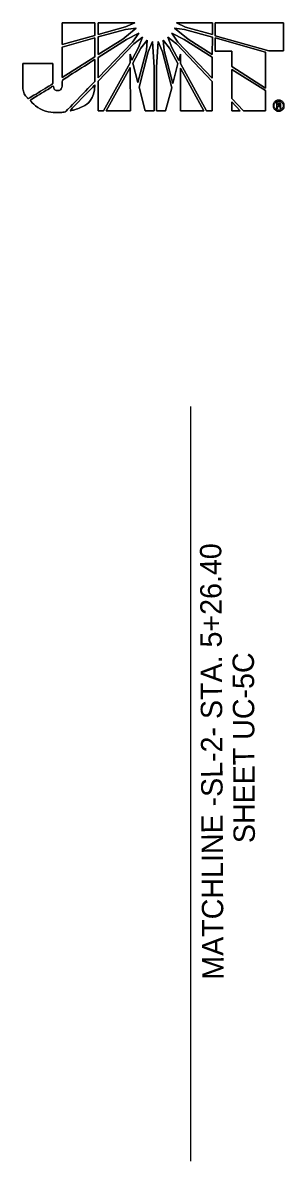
# Model space of a CAD drawing. Extents: x 0 to 2694, y -754 to 1499.
# Drawn here: x 3.571 to 3.775, y 0.255 to 1.142 of the extents above; entities that cross this region are included whole.
import ezdxf

# ---------------------------------------------------------------- set-up
doc = ezdxf.new("R2010")
doc.units = 0
doc.layers.add('Layer 1', color=7, linetype='Continuous')
doc.layers.add('UC Plan Profile Sheet 34 CELL', color=7, linetype='Continuous')

# ---------------------------------------------------------------- blocks, each defined once
blk = doc.blocks.new('block 2_1')
at = {"layer": 'Layer 1'}
for p, q in [((0.10682, 0.1325), (0.10682, 0.14026)), ((0.10682, 0.14026), (0.11852, 0.14026)), ((0.11852, 0.14026), (0.11852, 0.13575)), ((0.11973, 0.13613), (0.11973, 0.14032)), ((0.11973, 0.14032), (0.1329, 0.14032)), ((0.1329, 0.14032), (0.12954, 0.13884)), ((0.15109, 0.13878), (0.14781, 0.14032)), ((0.14781, 0.14032), (0.16078, 0.14026)), ((0.16078, 0.14026), (0.16078, 0.13606)), ((0.16169, 0.1358), (0.16169, 0.14032)), ((0.16169, 0.14032), (0.18629, 0.14032)), ((0.18629, 0.14032), (0.18629, 0.13024)), ((0.11852, 0.13575), (0.10682, 0.1325)), ((0.10682, 0.13161), (0.11852, 0.1349)), ((0.11852, 0.1349), (0.11852, 0.12812)), ((0.12954, 0.13884), (0.11973, 0.13613)), ((0.11973, 0.13523), (0.12954, 0.13793)), ((0.11973, 0.12889), (0.11973, 0.13523)), ((0.13337, 0.13839), (0.12852, 0.13445)), ((0.12954, 0.13793), (0.13337, 0.13839)), ((0.12987, 0.13432), (0.13433, 0.13658)), ((0.13433, 0.13658), (0.13207, 0.13341)), ((0.13257, 0.13277), (0.13568, 0.13517)), ((0.13568, 0.13517), (0.13425, 0.13142)), ((0.14476, 0.13517), (0.14787, 0.13277)), ((0.14619, 0.13142), (0.14476, 0.13517)), ((0.14613, 0.13658), (0.15065, 0.13432)), ((0.14839, 0.13335), (0.14613, 0.13658)), ((0.14715, 0.13839), (0.15076, 0.13793)), ((0.15206, 0.13438), (0.14715, 0.13839)), ((0.15076, 0.13793), (0.16078, 0.13517)), ((0.16078, 0.13606), (0.15109, 0.13878)), ((0.16078, 0.13517), (0.16071, 0.12897)), ((0.16169, 0.13567), (0.16169, 0.1358)), ((0.18106, 0.13024), (0.16169, 0.13567)), ((0.16169, 0.13497), (0.17982, 0.1298)), ((0.16169, 0.1349), (0.16169, 0.13497)), ((0.16169, 0.13019), (0.16169, 0.1349)), ((0.10682, 0.12071), (0.10682, 0.13161)), ((0.12852, 0.13445), (0.11973, 0.12889)), ((0.11973, 0.12787), (0.12987, 0.13432)), ((0.13207, 0.13341), (0.11973, 0.12057)), ((0.11973, 0.11933), (0.13257, 0.13277)), ((0.13425, 0.13142), (0.1318, 0.12696)), ((0.13213, 0.12586), (0.13505, 0.13115)), ((0.13505, 0.13115), (0.13736, 0.13412)), ((0.13736, 0.13412), (0.13704, 0.13051)), ((0.13769, 0.12986), (0.13929, 0.1336)), ((0.13929, 0.1336), (0.1398, 0.12437)), ((0.14063, 0.12437), (0.14123, 0.1336)), ((0.14123, 0.1336), (0.14277, 0.12986)), ((0.1431, 0.13412), (0.14536, 0.13115)), ((0.14348, 0.13038), (0.1431, 0.13412)), ((0.14536, 0.13115), (0.14839, 0.12567)), ((0.1487, 0.12677), (0.14619, 0.13142)), ((0.14787, 0.13277), (0.16071, 0.11922)), ((0.16071, 0.12043), (0.14839, 0.13335)), ((0.15065, 0.13432), (0.16071, 0.12793)), ((0.16071, 0.12897), (0.15206, 0.13438)), ((0.11852, 0.12812), (0.10682, 0.12071)), ((0.11973, 0.12057), (0.11973, 0.12787)), ((0.1318, 0.12696), (0.13122, 0.12908)), ((0.13122, 0.12908), (0.13122, 0.126)), ((0.13704, 0.13051), (0.134, 0.11883)), ((0.13439, 0.11721), (0.13769, 0.12986)), ((0.14277, 0.12986), (0.14613, 0.11702)), ((0.14652, 0.11856), (0.14348, 0.13038)), ((0.1493, 0.12908), (0.1487, 0.12677)), ((0.1493, 0.12567), (0.1493, 0.12908)), ((0.16071, 0.12793), (0.16071, 0.12043)), ((0.1677, 0.13019), (0.16169, 0.13019)), ((0.1677, 0.12457), (0.1677, 0.13019)), ((0.17982, 0.1298), (0.17982, 0.11688)), ((0.18629, 0.13024), (0.18106, 0.13024)), ((0.13122, 0.126), (0.12167, 0.10871)), ((0.12257, 0.10871), (0.13122, 0.12432)), ((0.13122, 0.12432), (0.1313, 0.10871)), ((0.134, 0.11883), (0.13213, 0.12586)), ((0.1398, 0.12437), (0.1398, 0.10877)), ((0.14063, 0.10877), (0.14063, 0.12437)), ((0.14839, 0.12567), (0.14652, 0.11856)), ((0.15864, 0.10871), (0.1493, 0.12567)), ((0.1493, 0.10877), (0.1493, 0.12399)), ((0.1493, 0.12399), (0.15768, 0.10877)), ((0.17982, 0.11688), (0.1677, 0.12457)), ((0.1677, 0.1236), (0.17982, 0.11597)), ((0.1677, 0.11314), (0.1677, 0.1236)), ((0.11973, 0.10871), (0.11973, 0.11933)), ((0.16071, 0.11922), (0.16071, 0.10871)), ((0.13659, 0.10877), (0.13439, 0.11721)), ((0.14613, 0.11702), (0.14387, 0.10877)), ((0.17982, 0.11597), (0.17982, 0.10871)), ((0.17189, 0.10871), (0.1677, 0.11314)), ((0.1677, 0.10871), (0.1677, 0.112)), ((0.1677, 0.112), (0.17073, 0.10871)), ((0.12167, 0.10871), (0.11973, 0.10871)), ((0.1313, 0.10871), (0.12257, 0.10871)), ((0.1398, 0.10877), (0.13659, 0.10877)), ((0.14387, 0.10877), (0.14063, 0.10877)), ((0.15768, 0.10877), (0.1493, 0.10877)), ((0.16071, 0.10871), (0.15864, 0.10871)), ((0.17073, 0.10871), (0.1677, 0.10871)), ((0.17982, 0.10871), (0.17189, 0.10871))]:
    blk.add_line(p, q, dxfattribs=at)
for points in [[(0.10682, 0.1325), (0.11852, 0.13575), (0.11852, 0.14026), (0.10682, 0.14026), (0.10682, 0.1325)], [(0.12954, 0.13884), (0.1329, 0.14032), (0.11973, 0.14032), (0.11973, 0.13613), (0.12954, 0.13884)], [(0.15109, 0.13878), (0.16078, 0.13606), (0.16078, 0.14026), (0.14781, 0.14032), (0.15109, 0.13878)], [(0.18629, 0.14032), (0.16169, 0.14032), (0.16169, 0.1358), (0.16169, 0.13567), (0.18106, 0.13024), (0.18629, 0.13024), (0.18629, 0.14032)], [(0.10682, 0.12071), (0.11852, 0.12812), (0.11852, 0.1349), (0.10682, 0.13161), (0.10682, 0.12071)], [(0.11973, 0.13523), (0.11973, 0.12889), (0.12852, 0.13445), (0.13337, 0.13839), (0.12954, 0.13793), (0.11973, 0.13523)], [(0.11973, 0.12787), (0.11973, 0.12057), (0.13207, 0.13341), (0.13433, 0.13658), (0.12987, 0.13432), (0.11973, 0.12787)], [(0.13568, 0.13517), (0.13257, 0.13277), (0.11973, 0.11933), (0.11973, 0.10871), (0.12167, 0.10871), (0.13122, 0.126), (0.13122, 0.12908), (0.1318, 0.12696), (0.13425, 0.13142), (0.13568, 0.13517)], [(0.14476, 0.13517), (0.14619, 0.13142), (0.1487, 0.12677), (0.1493, 0.12908), (0.1493, 0.12567), (0.15864, 0.10871), (0.16071, 0.10871), (0.16071, 0.11922), (0.14787, 0.13277), (0.14476, 0.13517)], [(0.14613, 0.13658), (0.14839, 0.13335), (0.16071, 0.12043), (0.16071, 0.12793), (0.15065, 0.13432), (0.14613, 0.13658)], [(0.14715, 0.13839), (0.15206, 0.13438), (0.16071, 0.12897), (0.16078, 0.13517), (0.15076, 0.13793), (0.14715, 0.13839)], [(0.16169, 0.13497), (0.16169, 0.1349), (0.16169, 0.13019), (0.1677, 0.13019), (0.1677, 0.12457), (0.17982, 0.11688), (0.17982, 0.1298), (0.16169, 0.13497)], [(0.13736, 0.13412), (0.13505, 0.13115), (0.13213, 0.12586), (0.134, 0.11883), (0.13704, 0.13051), (0.13736, 0.13412)], [(0.13769, 0.12986), (0.13439, 0.11721), (0.13659, 0.10877), (0.1398, 0.10877), (0.1398, 0.12437), (0.13929, 0.1336), (0.13769, 0.12986)], [(0.14123, 0.1336), (0.14063, 0.12437), (0.14063, 0.10877), (0.14387, 0.10877), (0.14613, 0.11702), (0.14277, 0.12986), (0.14123, 0.1336)], [(0.1431, 0.13412), (0.14348, 0.13038), (0.14652, 0.11856), (0.14839, 0.12567), (0.14536, 0.13115), (0.1431, 0.13412)], [(0.12257, 0.10871), (0.1313, 0.10871), (0.13122, 0.12432), (0.12257, 0.10871)], [(0.1493, 0.10877), (0.15768, 0.10877), (0.1493, 0.12399), (0.1493, 0.10877)], [(0.1677, 0.1236), (0.1677, 0.11314), (0.17189, 0.10871), (0.17982, 0.10871), (0.17982, 0.11597), (0.1677, 0.1236), (0.1677, 0.1236)], [(0.1677, 0.10871), (0.1677, 0.10871), (0.17073, 0.10871), (0.1677, 0.112), (0.1677, 0.10871)], [(0.18456, 0.11147), (0.18383, 0.11147), (0.18383, 0.10968), (0.18424, 0.10968), (0.18424, 0.11038), (0.18456, 0.11038), (0.18456, 0.1107), (0.18424, 0.1107), (0.18424, 0.11113), (0.18456, 0.11113), (0.18456, 0.11147)], [(0.18456, 0.11147), (0.18383, 0.11147), (0.18383, 0.10968), (0.18424, 0.10968), (0.18424, 0.11038), (0.18456, 0.11038)], [(0.18456, 0.1107), (0.18424, 0.1107), (0.18424, 0.11113), (0.18456, 0.11113)]]:
    blk.add_lwpolyline(points, dxfattribs=at)
for points in [[(0.10514, 0.11597), (0.10444, 0.11597), (0.10384, 0.11636), (0.10359, 0.11765), (0.10359, 0.11765), (0.09519, 0.11246), (0.09519, 0.11246), (0.09778, 0.10974), (0.10191, 0.10812), (0.10541, 0.10812), (0.10632, 0.10812), (0.10701, 0.10819), (0.10798, 0.10839), (0.10798, 0.10839), (0.11852, 0.11928), (0.11852, 0.11928), (0.11852, 0.11928), (0.11852, 0.12715), (0.11852, 0.12715), (0.11852, 0.12715), (0.10682, 0.11972), (0.10682, 0.11972), (0.10682, 0.11677), (0.1061, 0.11597), (0.10514, 0.11597)], [(0.10514, 0.11597), (0.1061, 0.11597), (0.10682, 0.11677), (0.10682, 0.11972), (0.10682, 0.11972), (0.11852, 0.12715), (0.11852, 0.12715), (0.11852, 0.12715), (0.11852, 0.11928), (0.11852, 0.11928), (0.11852, 0.11928), (0.10798, 0.10839), (0.10798, 0.10839), (0.10701, 0.10819), (0.10632, 0.10812), (0.10541, 0.10812), (0.10191, 0.10812), (0.09778, 0.10974), (0.09519, 0.11246), (0.09519, 0.11246), (0.10359, 0.11765), (0.10359, 0.11765), (0.10384, 0.11636), (0.10444, 0.11597), (0.10514, 0.11597)], [(0.10346, 0.12573), (0.10346, 0.12573), (0.09263, 0.12573), (0.09263, 0.12573), (0.09263, 0.12573), (0.09263, 0.11895), (0.09263, 0.11895), (0.09263, 0.11895), (0.09263, 0.11823), (0.09263, 0.11823), (0.09263, 0.11611), (0.09332, 0.11443), (0.09456, 0.11302), (0.09456, 0.11302), (0.10346, 0.11843), (0.10346, 0.11856), (0.10346, 0.11856), (0.10346, 0.12573), (0.10346, 0.12573)], [(0.10346, 0.12573), (0.10346, 0.12573), (0.10346, 0.11856), (0.10346, 0.11856), (0.10346, 0.11843), (0.09456, 0.11302), (0.09456, 0.11302), (0.09332, 0.11443), (0.09263, 0.11611), (0.09263, 0.11823), (0.09263, 0.11823), (0.09263, 0.11895), (0.09263, 0.11895), (0.09263, 0.11895), (0.09263, 0.12573), (0.09263, 0.12573), (0.09263, 0.12573), (0.10346, 0.12573), (0.10346, 0.12573)], [(0.11852, 0.11804), (0.11852, 0.11804), (0.1094, 0.10864), (0.1094, 0.10864), (0.11386, 0.10974), (0.11831, 0.11269), (0.11852, 0.11804)], [(0.11852, 0.11804), (0.11831, 0.11269), (0.11386, 0.10974), (0.1094, 0.10864), (0.1094, 0.10864), (0.11852, 0.11804), (0.11852, 0.11804)], [(0.18456, 0.10859), (0.18403, 0.10859), (0.18355, 0.10878), (0.18316, 0.10917), (0.18277, 0.10955), (0.18258, 0.11002), (0.18258, 0.11057), (0.18258, 0.11113), (0.18277, 0.1116), (0.18316, 0.11195), (0.18355, 0.11233), (0.18401, 0.11252), (0.18456, 0.11252), (0.18456, 0.11252), (0.18456, 0.11215), (0.18456, 0.11215), (0.18412, 0.11215), (0.18375, 0.112), (0.18344, 0.11171), (0.18313, 0.1114), (0.18297, 0.11101), (0.18297, 0.11057), (0.18297, 0.11013), (0.18313, 0.10974), (0.18344, 0.10943), (0.18375, 0.10913), (0.18412, 0.10898), (0.18456, 0.10898), (0.18456, 0.10898), (0.18456, 0.10859), (0.18456, 0.10859), (0.18456, 0.10859), (0.18456, 0.10859), (0.18456, 0.10859)], [(0.18456, 0.11252), (0.18401, 0.11252), (0.18355, 0.11233), (0.18316, 0.11195), (0.18277, 0.1116), (0.18258, 0.11113), (0.18258, 0.11057), (0.18258, 0.11002), (0.18277, 0.10955), (0.18316, 0.10917), (0.18355, 0.10878), (0.18403, 0.10859), (0.18456, 0.10859)], [(0.18456, 0.10898), (0.18412, 0.10898), (0.18375, 0.10913), (0.18344, 0.10943), (0.18313, 0.10974), (0.18297, 0.11013), (0.18297, 0.11057), (0.18297, 0.11101), (0.18313, 0.1114), (0.18344, 0.11171), (0.18375, 0.112), (0.18412, 0.11215), (0.18456, 0.11215)], [(0.18656, 0.11057), (0.18656, 0.11002), (0.18637, 0.10955), (0.18599, 0.10916), (0.1856, 0.10878), (0.18513, 0.10859), (0.18458, 0.10859), (0.18458, 0.10859), (0.18458, 0.10859), (0.18456, 0.10859), (0.18456, 0.10859), (0.18456, 0.10898), (0.18456, 0.10898), (0.18458, 0.10898), (0.18458, 0.10898), (0.18458, 0.10898), (0.18502, 0.10898), (0.18539, 0.10913), (0.1857, 0.10943), (0.18601, 0.10974), (0.18617, 0.11013), (0.18617, 0.11057), (0.18617, 0.11101), (0.18601, 0.1114), (0.1857, 0.11171), (0.18539, 0.112), (0.18502, 0.11215), (0.18456, 0.11215), (0.18456, 0.11215), (0.18456, 0.11252), (0.18456, 0.11252), (0.18512, 0.11252), (0.18559, 0.11233), (0.18598, 0.11195), (0.18637, 0.1116), (0.18656, 0.11113), (0.18656, 0.11057), (0.18656, 0.11057), (0.18656, 0.11057), (0.18656, 0.11057)], [(0.18656, 0.11057), (0.18656, 0.11113), (0.18637, 0.1116), (0.18598, 0.11195), (0.18559, 0.11233), (0.18512, 0.11252), (0.18456, 0.11252)], [(0.18456, 0.11215), (0.18502, 0.11215), (0.18539, 0.112), (0.1857, 0.11171), (0.18601, 0.1114), (0.18617, 0.11101), (0.18617, 0.11057), (0.18617, 0.11013), (0.18601, 0.10974), (0.1857, 0.10943), (0.18539, 0.10913), (0.18502, 0.10898), (0.18458, 0.10898), (0.18458, 0.10898), (0.18458, 0.10898), (0.18456, 0.10898)], [(0.18456, 0.11038), (0.18456, 0.11038), (0.18456, 0.1107), (0.18456, 0.1107), (0.18456, 0.1107), (0.18458, 0.1107), (0.18458, 0.1107), (0.18484, 0.1107), (0.18497, 0.11078), (0.18497, 0.11093), (0.18497, 0.11106), (0.18485, 0.11113), (0.18461, 0.11113), (0.18461, 0.11113), (0.18456, 0.11113), (0.18456, 0.11113), (0.18456, 0.11113), (0.18456, 0.11147), (0.18456, 0.11147), (0.18456, 0.11147), (0.18468, 0.11147), (0.18468, 0.11147), (0.18513, 0.11147), (0.18536, 0.11129), (0.18536, 0.11093), (0.18536, 0.11077), (0.18529, 0.11064), (0.18515, 0.11054), (0.18526, 0.11048), (0.18533, 0.11033), (0.18534, 0.1101), (0.18534, 0.1101), (0.18534, 0.11), (0.18534, 0.11), (0.18534, 0.11), (0.18536, 0.10994), (0.18536, 0.10994), (0.18536, 0.10994), (0.18536, 0.10987), (0.18536, 0.10987), (0.18536, 0.10987), (0.18541, 0.10968), (0.18541, 0.10968), (0.18541, 0.10968), (0.18503, 0.10968), (0.18503, 0.10968), (0.18499, 0.10978), (0.18495, 0.10987), (0.18495, 0.11), (0.18495, 0.11017), (0.18494, 0.11026), (0.18489, 0.11031), (0.18484, 0.11034), (0.18474, 0.11038), (0.18458, 0.11038), (0.18458, 0.11038), (0.18456, 0.11038), (0.18456, 0.11038)], [(0.18456, 0.11038), (0.18456, 0.11038), (0.18458, 0.11038), (0.18458, 0.11038), (0.18474, 0.11038), (0.18484, 0.11034), (0.18489, 0.11031), (0.18494, 0.11026), (0.18495, 0.11017), (0.18495, 0.11), (0.18495, 0.10987), (0.18499, 0.10978), (0.18503, 0.10968), (0.18503, 0.10968), (0.18541, 0.10968), (0.18541, 0.10968), (0.18541, 0.10968), (0.18536, 0.10987), (0.18536, 0.10987), (0.18536, 0.10987), (0.18536, 0.10994), (0.18536, 0.10994), (0.18536, 0.10994), (0.18534, 0.11), (0.18534, 0.11), (0.18534, 0.11), (0.18534, 0.1101), (0.18534, 0.1101), (0.18533, 0.11033), (0.18526, 0.11048), (0.18515, 0.11054), (0.18529, 0.11064), (0.18536, 0.11077), (0.18536, 0.11093), (0.18536, 0.11129), (0.18513, 0.11147), (0.18468, 0.11147), (0.18468, 0.11147), (0.18456, 0.11147), (0.18456, 0.11147)], [(0.18456, 0.11113), (0.18456, 0.11113), (0.18461, 0.11113), (0.18461, 0.11113), (0.18485, 0.11113), (0.18497, 0.11106), (0.18497, 0.11093), (0.18497, 0.11078), (0.18484, 0.1107), (0.18458, 0.1107), (0.18458, 0.1107), (0.18456, 0.1107), (0.18456, 0.1107)], [(0.18456, 0.10859), (0.18458, 0.10859), (0.18458, 0.10859), (0.18458, 0.10859), (0.18513, 0.10859), (0.1856, 0.10878), (0.18599, 0.10916), (0.18637, 0.10955), (0.18656, 0.11002), (0.18656, 0.11057)]]:
    blk.add_open_spline(points, degree=3, dxfattribs=at)

msp = doc.modelspace()

# ---------------------------------------------------------------- linework, layer by layer
at = {"layer": 'UC Plan Profile Sheet 34 CELL'}
msp.add_line((3.70261, 0.25512), (3.70253, 0.84317), dxfattribs=at)

# ---------------------------------------------------------------- block references
at = {"layer": 'UC Plan Profile Sheet 34 CELL', "xscale": 2.170686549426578, "yscale": 2.170686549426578}
msp.add_blockref('block 2_1', (3.37041, 0.83748), dxfattribs=at)

# ---------------------------------------------------------------- texts
at = {"layer": 'UC Plan Profile Sheet 34 CELL'}
for s, p in [('MATCHLINE -SL-2- STA. 5+26.40', (3.7281, 0.3966)), ('SHEET UC-5C', (3.75253, 0.50298))]:
    msp.add_text(s, height=0.0166667, rotation=90.30681, dxfattribs=at).set_placement(p)

doc.saveas('drawing.dxf')
